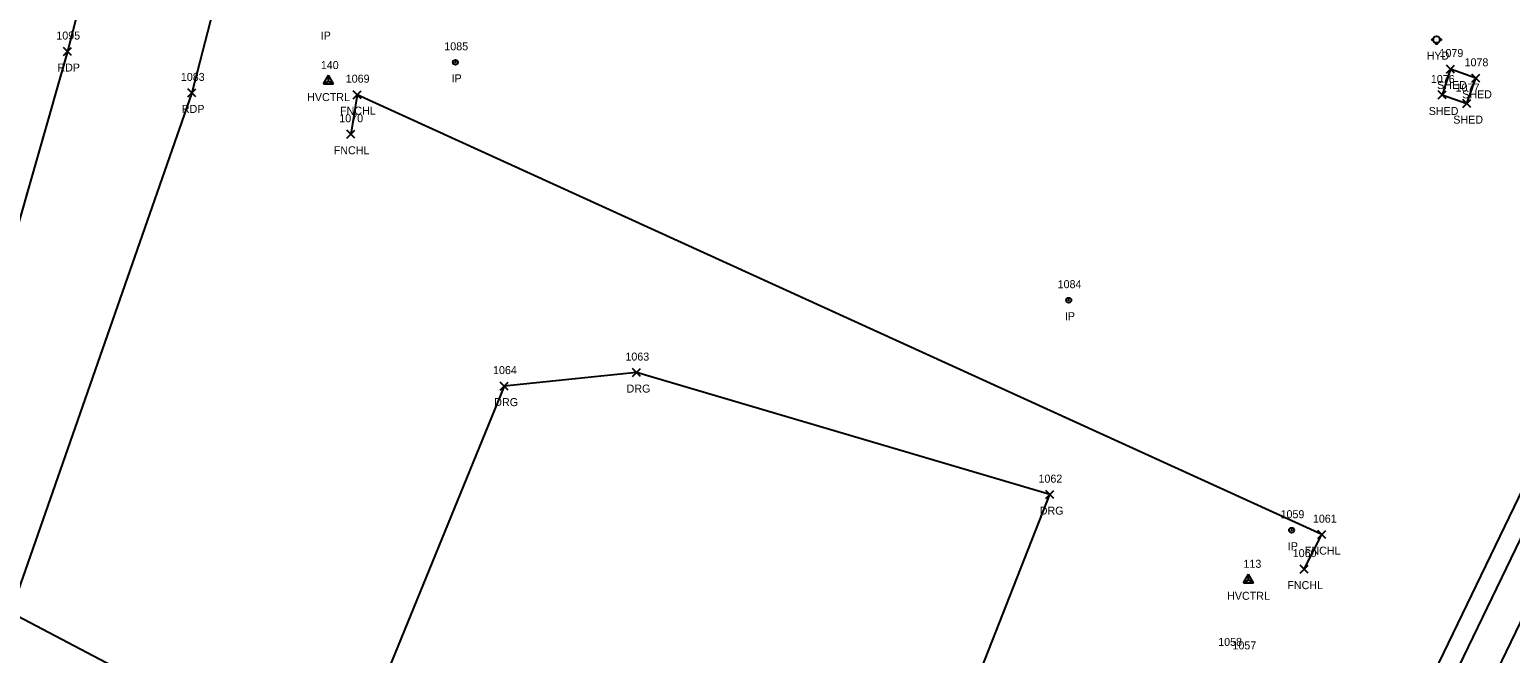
# Model space of a CAD drawing. Extents: x 1767353 to 1772625, y 740790 to 747702.
# Drawn here: x 1770255.6 to 1770625.6, y 742981 to 743136.9 of the extents above; entities that cross this region are included whole.
import ezdxf

# ---------------------------------------------------------------- set-up
doc = ezdxf.new("R2010")
doc.units = 0
for name, color, linetype in [('C_A', 7, 'Continuous'), ('C_I', 7, 'Continuous'), ('CPSM', 7, 'Continuous'), ('L_A', 7, 'Continuous'), ('L_I', 7, 'Continuous'), ('L_TIC', 7, 'Continuous'), ('LBC', 7, 'Continuous'), ('LFNC', 7, 'Continuous'), ('M_A', 7, 'Continuous'), ('M_I', 7, 'Continuous'), ('MPIR', 7, 'Continuous'), ('P_A', 7, 'Continuous'), ('P_I', 7, 'Continuous'), ('P_TIC', 7, 'Continuous'), ('PET', 7, 'Continuous'), ('R_A', 7, 'Continuous'), ('R_I', 7, 'Continuous'), ('R_TIC', 7, 'Continuous'), ('RDG', 7, 'Continuous'), ('RDP', 7, 'Continuous'), ('RR', 7, 'Continuous'), ('U_A', 7, 'Continuous'), ('UWFH', 7, 'Continuous')]:
    doc.layers.add(name, color=color, linetype=linetype)

msp = doc.modelspace()

# ---------------------------------------------------------------- linework, layer by layer
at = {"layer": 'CPSM'}
for p, q in [((1770329.01, 743123.33), (1770330.26, 743125.5)), ((1770329.01, 743123.33), (1770330.26, 743125.5)), ((1770329.01, 743123.33), (1770330.26, 743125.5)), ((1770329.01, 743123.33), (1770330.26, 743125.5)), ((1770329.01, 743123.33), (1770330.26, 743125.5)), ((1770329.01, 743123.33), (1770330.26, 743125.5)), ((1770329.01, 743123.33), (1770330.26, 743124.05)), ((1770329.01, 743123.33), (1770330.26, 743124.05)), ((1770329.01, 743123.33), (1770330.26, 743124.05)), ((1770329.01, 743123.33), (1770330.26, 743124.05)), ((1770329.01, 743123.33), (1770330.26, 743124.05)), ((1770329.01, 743123.33), (1770330.26, 743124.05)), ((1770331.51, 743123.33), (1770330.26, 743125.5)), ((1770330.26, 743124.05), (1770330.26, 743125.5)), ((1770331.51, 743123.33), (1770330.26, 743125.5)), ((1770330.26, 743124.05), (1770330.26, 743125.5)), ((1770331.51, 743123.33), (1770330.26, 743125.5)), ((1770330.26, 743124.05), (1770330.26, 743125.5)), ((1770331.51, 743123.33), (1770330.26, 743125.5)), ((1770330.26, 743124.05), (1770330.26, 743125.5)), ((1770331.51, 743123.33), (1770330.26, 743125.5)), ((1770330.26, 743124.05), (1770330.26, 743125.5)), ((1770331.51, 743123.33), (1770330.26, 743125.5)), ((1770330.26, 743124.05), (1770330.26, 743125.5)), ((1770330.26, 743124.05), (1770330.26, 743124.05)), ((1770330.26, 743124.05), (1770331.51, 743123.33)), ((1770330.26, 743124.05), (1770330.26, 743124.05)), ((1770330.26, 743124.05), (1770331.51, 743123.33)), ((1770330.26, 743124.05), (1770330.26, 743124.05)), ((1770330.26, 743124.05), (1770331.51, 743123.33)), ((1770330.26, 743124.05), (1770330.26, 743124.05)), ((1770330.26, 743124.05), (1770331.51, 743123.33)), ((1770330.26, 743124.05), (1770330.26, 743124.05)), ((1770330.26, 743124.05), (1770331.51, 743123.33)), ((1770330.26, 743124.05), (1770330.26, 743124.05)), ((1770330.26, 743124.05), (1770331.51, 743123.33)), ((1770329.01, 743123.33), (1770331.51, 743123.33)), ((1770329.01, 743123.33), (1770331.51, 743123.33)), ((1770329.01, 743123.33), (1770331.51, 743123.33)), ((1770329.01, 743123.33), (1770331.51, 743123.33)), ((1770329.01, 743123.33), (1770331.51, 743123.33)), ((1770329.01, 743123.33), (1770331.51, 743123.33)), ((1770558.9, 742998.65), (1770560.15, 743000.82)), ((1770558.9, 742998.65), (1770560.15, 742999.38)), ((1770558.9, 742998.65), (1770561.4, 742998.65)), ((1770561.4, 742998.65), (1770560.15, 743000.82)), ((1770560.15, 742999.38), (1770560.15, 743000.82)), ((1770560.15, 742999.38), (1770560.15, 742999.38)), ((1770560.15, 742999.38), (1770561.4, 742998.65))]:
    msp.add_line(p, q, dxfattribs=at)
at = {"layer": 'L_TIC'}
for points in [[(1770609.69, 743126.06), (1770611.69, 743128.06)], [(1770611.69, 743126.06), (1770609.69, 743128.06)], [(1770615.95, 743123.74), (1770617.95, 743125.74)], [(1770617.95, 743123.74), (1770615.95, 743125.74)], [(1770336.43, 743119.65), (1770338.43, 743121.65)], [(1770338.43, 743119.65), (1770336.43, 743121.65)], [(1770607.57, 743119.57), (1770609.57, 743121.57)], [(1770609.57, 743119.57), (1770607.57, 743121.57)], [(1770613.72, 743117.41), (1770615.72, 743119.41)], [(1770615.72, 743117.41), (1770613.72, 743119.41)], [(1770334.85, 743109.75), (1770336.85, 743111.75)], [(1770336.85, 743109.75), (1770334.85, 743111.75)], [(1770577.52, 743009.67), (1770579.52, 743011.67)], [(1770579.52, 743009.67), (1770577.52, 743011.67)], [(1770573.13, 743001.05), (1770575.13, 743003.05)], [(1770575.13, 743001.05), (1770573.13, 743003.05)]]:
    msp.add_lwpolyline(points, dxfattribs=at)
at = {"layer": 'LBC'}
for points in [[(1770608.57, 743120.57), (1770614.72, 743118.41), (1770616.95, 743124.74), (1770610.69, 743127.06)], [(1770610.69, 743127.06), (1770608.57, 743120.57)]]:
    msp.add_lwpolyline(points, dxfattribs=at)
at = {"layer": 'LFNC'}
msp.add_lwpolyline([(1770574.13, 743002.05), (1770578.52, 743010.67), (1770337.43, 743120.65), (1770335.85, 743110.75)], dxfattribs=at)
at = {"layer": 'MPIR'}
for centre, radius in [((1770362, 743128.74), 0.625), ((1770362, 743128.74), 0.0833), ((1770515.26, 743069.28), 0.625), ((1770515.26, 743069.28), 0.0833), ((1770570.96, 743011.78), 0.625), ((1770570.96, 743011.78), 0.0833)]:
    msp.add_circle(centre, radius, dxfattribs=at)
at = {"layer": 'P_TIC'}
for points in [[(1770264.05, 743130.43), (1770266.05, 743132.43)], [(1770266.05, 743130.43), (1770264.05, 743132.43)], [(1770295.17, 743120.09), (1770297.17, 743122.09)], [(1770297.17, 743120.09), (1770295.17, 743122.09)]]:
    msp.add_lwpolyline(points, dxfattribs=at)
at = {"layer": 'PET'}
for points in [[(1770287.36, 743218.01), (1770265.05, 743131.43), (1770236.51, 743031.56), (1770219.34, 742972.95), (1770201.78, 742917.74), (1770184.32, 742871.03), (1770170.89, 742832.33), (1770155.31, 742796.84), (1770127.15, 742730.43), (1770071.7, 742605.94), (1770068.18, 742600.07), (1770059.84, 742596.32), (1770058.18, 742592.27), (1770056.9, 742590.58), (1770055.34, 742589.72), (1770052.72, 742590.21), (1770049.12, 742591.83), (1770036.26, 742597.45)], [(1770318.5, 743207.69), (1770296.17, 743121.09), (1770250.85, 742991.18), (1770237.09, 742941.3), (1770205.64, 742845.48), (1770184.95, 742786.57), (1770170.21, 742755.02), (1770147.48, 742699.94), (1770126.77, 742647.43)]]:
    msp.add_lwpolyline(points, dxfattribs=at)
at = {"layer": 'R_TIC'}
for points in [[(1770406.29, 743050.18), (1770408.29, 743052.18)], [(1770408.29, 743050.18), (1770406.29, 743052.18)], [(1770373.22, 743046.8), (1770375.22, 743048.8)], [(1770375.22, 743046.8), (1770373.22, 743048.8)], [(1770509.52, 743019.67), (1770511.52, 743021.67)], [(1770511.52, 743019.67), (1770509.52, 743021.67)]]:
    msp.add_lwpolyline(points, dxfattribs=at)
at = {"layer": 'RDG'}
msp.add_lwpolyline([(1770316.71, 742759.3), (1770329.52, 742719.08), (1770365.82, 742714.67), (1770393.27, 742721.22), (1770410.95, 742730.87), (1770457.92, 742812.25), (1770453.67, 742859.09), (1770466.3, 742908.02), (1770510.52, 743020.67), (1770407.29, 743051.18), (1770374.22, 743047.8), (1770339.87, 742963.82)], dxfattribs=at)
at = {"layer": 'RDP'}
msp.add_lwpolyline([(1770358.02, 742818.47), (1770383, 742815.07), (1770381.79, 742805.76), (1770402.35, 742803.35), (1770416, 742845.87), (1770417.24, 742925.38), (1770417.05, 742964.46), (1770339.87, 742963.82), (1770324.43, 742957.55), (1770311.28, 742959.37), (1770250.85, 742991.18)], dxfattribs=at)
at = {"layer": 'RR'}
for points in [[(1770221.78, 741982.04), (1770226.9, 742005.14), (1770231.58, 742026.58), (1770238.97, 742057.62), (1770247.46, 742091.31), (1770255.17, 742120.86), (1770262.38, 742147.12), (1770270.79, 742177.04), (1770278.58, 742203.25), (1770285.57, 742226.22), (1770292.18, 742247.12), (1770303.7, 742282.6), (1770315.3, 742316.87), (1770330.35, 742359.31), (1770344.25, 742396.26), (1770362.68, 742444.08), (1770381.25, 742488.48), (1770399.89, 742531.75), (1770427.72, 742593.02), (1770459.92, 742661.06), (1770775.2, 743314.07), (1770996.39, 743772.66), (1771192.02, 744177.67), (1771329.71, 744462.72)], [(1770217.88, 741982.89), (1770224.63, 742006.05), (1770231.58, 742026.58), (1770242.49, 742057.3), (1770253.86, 742089.03), (1770263.22, 742117.76), (1770271, 742143.83), (1770279.57, 742174.49), (1770286.79, 742199.43), (1770293.9, 742223.08), (1770300.84, 742244.95), (1770311.67, 742279.15), (1770323.34, 742314.32), (1770337.98, 742356.11), (1770351.9, 742393.8), (1770370.52, 742441.44), (1770388.76, 742485.07), (1770407.79, 742528.71), (1770435.51, 742589.24), (1770468.44, 742657.89), (1770783.17, 743309.95), (1771004.51, 743768.91), (1771200.35, 744174.24), (1771337.45, 744458.43)], [(1770217.02, 741983.21), (1770222.11, 742006.18), (1770226.99, 742028.12), (1770234.33, 742059.23), (1770242.65, 742092.71), (1770250.33, 742121.94), (1770257.59, 742148.49), (1770265.95, 742178.19), (1770273.77, 742204.67), (1770280.68, 742227.53), (1770287.46, 742248.27), (1770299.11, 742284.6), (1770310.51, 742317.94), (1770325.96, 742361.53), (1770339.5, 742397.74), (1770358.03, 742445.88), (1770376.8, 742490.97), (1770395.2, 742533.35), (1770423.54, 742595.68), (1770455.2, 742662.62), (1770770.92, 743316.68), (1770991.9, 743774.87)]]:
    msp.add_lwpolyline(points, dxfattribs=at)
at = {"layer": 'UWFH'}
msp.add_line((1770607.18, 743134.4), (1770607.18, 743134.4), dxfattribs=at)
for centre, radius in [((1770607.18, 743134.4), 0.833), ((1770606.18, 743134.4), 0.167), ((1770607.18, 743133.4), 0.167), ((1770608.18, 743134.4), 0.167)]:
    msp.add_circle(centre, radius, dxfattribs=at)

# ---------------------------------------------------------------- texts
at = {"layer": 'C_A'}
for p in [(1770324.95, 743119.05), (1770324.95, 743119.05), (1770324.95, 743119.05), (1770324.95, 743119.05), (1770324.95, 743119.05), (1770324.95, 743119.05), (1770554.84, 742994.38)]:
    msp.add_text('HVCTRL', height=2, dxfattribs=at).set_placement(p)
at = {"layer": 'C_I'}
for s, p in [('140', (1770328.37, 743127.05)), ('140', (1770328.37, 743127.05)), ('140', (1770328.37, 743127.05)), ('140', (1770328.37, 743127.05)), ('140', (1770328.37, 743127.05)), ('140', (1770328.37, 743127.05)), ('113', (1770558.92, 743002.38))]:
    msp.add_text(s, height=2, dxfattribs=at).set_placement(p)
at = {"layer": 'L_A'}
for s, p in [('SHED', (1770607.32, 743122.06)), ('SHED', (1770613.58, 743119.74)), ('FNCHL', (1770333.17, 743115.65)), ('SHED', (1770605.21, 743115.57)), ('SHED', (1770611.36, 743113.41)), ('FNCHL', (1770331.6, 743105.75)), ('FNCHL', (1770574.27, 743005.67)), ('FNCHL', (1770569.88, 742997.05))]:
    msp.add_text(s, height=2, dxfattribs=at).set_placement(p)
at = {"layer": 'L_I'}
for s, p in [('1079', (1770607.91, 743130.06)), ('1078', (1770614.17, 743127.74)), ('1069', (1770334.6, 743123.65)), ('1076', (1770605.74, 743123.57)), ('1077', (1770611.95, 743121.41)), ('1070', (1770332.99, 743113.75)), ('1061', (1770576.27, 743013.67)), ('1060', (1770571.23, 743005.05)), ('1058', (1770552.61, 742982.86)), ('1057', (1770556.17, 742981.99))]:
    msp.add_text(s, height=2, dxfattribs=at).set_placement(p)
at = {"layer": 'M_A'}
for p in [(1770328.34, 743134.43), (1770361.04, 743123.74), (1770514.31, 743064.28), (1770570.01, 743006.78)]:
    msp.add_text('IP', height=2, dxfattribs=at).set_placement(p)
at = {"layer": 'M_I'}
for s, p in [('1085', (1770359.23, 743131.74)), ('1084', (1770512.49, 743072.28)), ('1059', (1770568.19, 743014.78))]:
    msp.add_text(s, height=2, dxfattribs=at).set_placement(p)
at = {"layer": 'P_A'}
for p in [(1770262.54, 743126.43), (1770293.65, 743116.09)]:
    msp.add_text('RDP', height=2, dxfattribs=at).set_placement(p)
at = {"layer": 'P_I'}
for s, p in [('1095', (1770262.28, 743134.43)), ('1083', (1770293.39, 743124.09))]:
    msp.add_text(s, height=2, dxfattribs=at).set_placement(p)
at = {"layer": 'R_A'}
for p in [(1770404.78, 743046.18), (1770371.71, 743042.8), (1770508.01, 743015.67)]:
    msp.add_text('DRG', height=2, dxfattribs=at).set_placement(p)
at = {"layer": 'R_I'}
for s, p in [('1063', (1770404.48, 743054.18)), ('1064', (1770371.4, 743050.8)), ('1062', (1770507.7, 743023.67))]:
    msp.add_text(s, height=2, dxfattribs=at).set_placement(p)
at = {"layer": 'U_A'}
msp.add_text('HYD', height=2, dxfattribs=at).set_placement((1770604.7, 743129.4))

doc.saveas('drawing.dxf')
